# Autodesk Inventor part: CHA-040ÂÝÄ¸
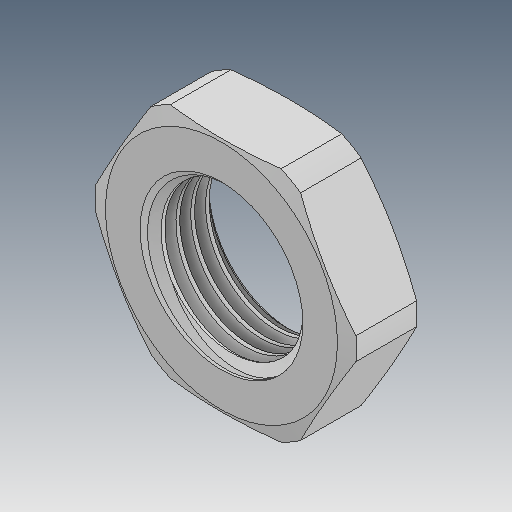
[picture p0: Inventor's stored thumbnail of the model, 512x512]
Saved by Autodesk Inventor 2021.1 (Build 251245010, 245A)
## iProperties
Created: 2019-05
Part Number: CHA-040ÂÝÄ¸
Material: Ogólny
Document SubType Name: Modeling
Designer: user
Density: 1 g/cm^3
Appearance: Domyślna
Author: user
Revision Number: ÈÎºÎ
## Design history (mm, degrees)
feature "¾µÏò1"
node "Bryła1"
